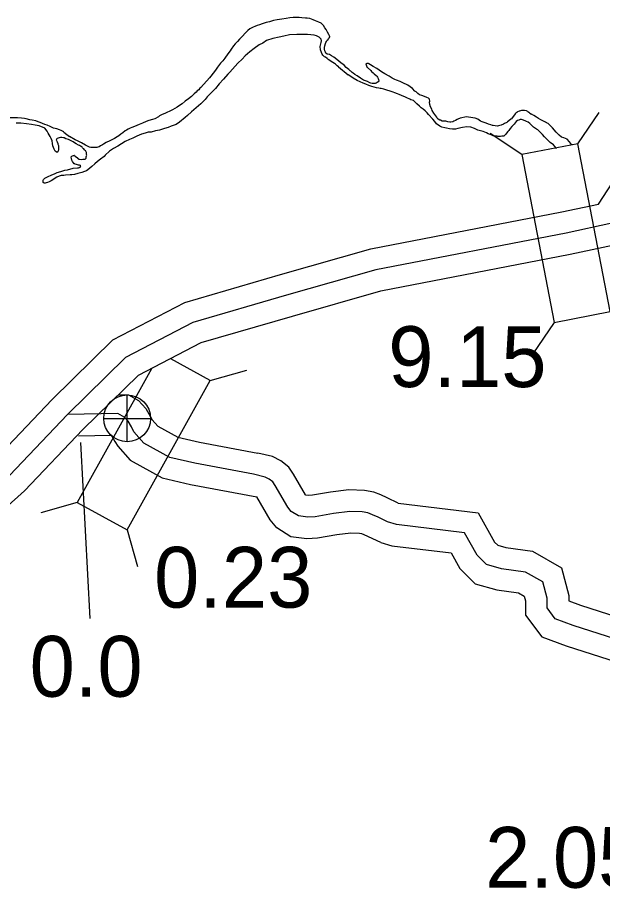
# Model space of a CAD drawing. Extents: x -83719 to 153526, y -11835 to 11446.
# Drawn here: x -4265.7 to -4130.2, y -1225.7 to -1023.9 of the extents above; entities that cross this region are included whole.
import ezdxf

# ---------------------------------------------------------------- set-up
doc = ezdxf.new("R2010")
doc.units = 0
for name, color, linetype in [('Level 10', 7, 'Continuous'), ('Level 20', 7, 'Continuous'), ('Level 25', 7, 'Continuous'), ('Level 26', 7, 'Continuous'), ('Level 58', 7, 'Continuous'), ('Level 59', 7, 'Continuous'), ('Level 9', 7, 'Continuous')]:
    doc.layers.add(name, color=color, linetype=linetype)

msp = doc.modelspace()

# ---------------------------------------------------------------- linework, layer by layer
at = {"layer": 'Level 10'}
msp.add_line((-4243.2, -1122.18), (-4242.49, -1123.21), dxfattribs=at)
for points in [[(-4271.03, -1126.42), (-4257.71, -1112.38), (-4243.65, -1098.56), (-4226.95, -1089.91), (-4204.78, -1083.46), (-4183.91, -1077.51), (-4139.71, -1068.96), (-4131.18, -1067.13), (-4120.41, -1050.53), (-4118.86, -1047.55), (-4114.95, -1043.07), (-4110.13, -1040.96), (-4104.85, -1040.74), (-4096.35, -1040.89), (-4088.26, -1041.21), (-4080.02, -1042.14), (-4050.59, -1033.6), (-4044.72, -1032.42), (-4008.49, -1036.91), (-3996.25, -1040.57)], [(-4268.64, -1137.7), (-4264.05, -1133.6), (-4250.57, -1119.39), (-4237.71, -1106.75), (-4223.21, -1099.24), (-4202.01, -1093.07), (-4181.59, -1087.25), (-4137.71, -1078.76), (-4125.04, -1076.04), (-4111.76, -1055.57), (-4110.54, -1053.23), (-4108.89, -1051.34), (-4107.84, -1050.88), (-4104.73, -1050.75), (-4096.64, -1050.89), (-4089.02, -1051.19), (-4079.15, -1052.3), (-4048.21, -1043.32), (-4044.34, -1042.55), (-4010.55, -1046.73), (-3999.11, -1050.15)], [(-4242.33, -1111.32), (-4240.01, -1111.3), (-4237.7, -1112.62), (-4235.96, -1114.48), (-4234.54, -1117.11)], [(-4234.54, -1117.11), (-4233.25, -1118.56), (-4228.61, -1121.14), (-4223.6, -1122.29), (-4210.05, -1124.85)], [(-4251.56, -1120.83), (-4243.98, -1120.68)], [(-4243.98, -1120.68), (-4243.75, -1121.1), (-4243.2, -1122.18)], [(-4242.49, -1123.21), (-4239.6, -1126.47), (-4232.23, -1130.57), (-4225.66, -1132.08), (-4210.31, -1134.98)], [(-4177.54, -1136.41), (-4180.1, -1135.18), (-4181.59, -1134.5), (-4183.23, -1133.89), (-4185.33, -1133.47), (-4189.02, -1133.34), (-4193.25, -1133.9), (-4197.39, -1134.59), (-4198.33, -1134.65), (-4198.93, -1134.57), (-4199.02, -1134.51), (-4199.02, -1134.51), (-4201.82, -1129.69), (-4202.89, -1128.09), (-4204.71, -1126.63), (-4206.66, -1125.65), (-4210.05, -1124.85)], [(-4181.6, -1145.51), (-4185.43, -1143.74), (-4185.97, -1143.54), (-4186.49, -1143.43), (-4188.54, -1143.36), (-4191.77, -1143.79), (-4196.26, -1144.54), (-4198.69, -1144.69), (-4202.39, -1144.2), (-4205.67, -1142.15), (-4207.24, -1140.27), (-4210.31, -1134.98)], [(-4177.54, -1136.41), (-4159.05, -1138.66), (-4155.25, -1145.45), (-4154.51, -1146.19), (-4152.63, -1146.73), (-4146.48, -1147.58), (-4139.75, -1151.38), (-4138.08, -1157.84), (-4138.08, -1159.04), (-4138.08, -1159.05), (-4135.37, -1160.08), (-4109.86, -1168.26), (-4103.97, -1180.37), (-4102.15, -1182.77), (-4098.56, -1184.79), (-4092.35, -1186.67), (-4087.42, -1189.5), (-4086.63, -1189.57), (-4073.87, -1188.11), (-4053.9, -1180.49), (-4031.8, -1175.51), (-4007.33, -1172.49), (-3998.66, -1171.4), (-3993.94, -1172.24)], [(-4181.6, -1145.51), (-4179.03, -1146.3), (-4165.3, -1147.97), (-4163.3, -1151.55), (-4159.74, -1155.1), (-4154.7, -1156.54), (-4149.74, -1157.22), (-4148.37, -1158), (-4148.08, -1159.09), (-4148.1, -1162.35), (-4144.34, -1167.37), (-4138.67, -1169.52), (-4116.98, -1176.48)]]:
    msp.add_lwpolyline(points, dxfattribs=at)
at = {"layer": 'Level 20'}
for p, q in [((-4135.99, -1053.17), (-4131.06, -1045.88)), ((-4148.95, -1055.67), (-4156.24, -1050.75)), ((-4141.43, -1094.55), (-4146.36, -1101.84)), ((-4221.1, -1108.03), (-4230.21, -1102.97)), ((-4234.67, -1105.27), (-4251.86, -1136.25)), ((-4221.1, -1108.03), (-4212.64, -1105.61)), ((-4240.32, -1142.65), (-4221.1, -1108.03)), ((-4251.86, -1136.25), (-4260.32, -1138.67)), ((-4251.86, -1136.25), (-4240.32, -1142.65)), ((-4240.32, -1142.65), (-4237.9, -1151.11))]:
    msp.add_line(p, q, dxfattribs=at)
msp.add_lwpolyline([(-4148.95, -1055.67), (-4141.43, -1094.55), (-4128.47, -1092.05), (-4135.99, -1053.17)], close=True, dxfattribs=at)
at = {"layer": 'Level 25'}
msp.add_line((-4251.13, -1122.41), (-4248.99, -1163.16), dxfattribs=at)
at = {"layer": 'Level 26'}
for p, q in [((-4240.32, -1122.21), (-4240.32, -1111.37)), ((-4245.73, -1116.79), (-4234.9, -1116.79))]:
    msp.add_line(p, q, dxfattribs=at)
msp.add_circle((-4240.32, -1116.79), 5.42, dxfattribs=at)
at = {"layer": 'Level 59'}
for points in [[(-3997.68, -1045.36), (-4009.52, -1041.82), (-4044.53, -1037.49), (-4049.4, -1038.46), (-4079.58, -1047.22), (-4088.64, -1046.2), (-4096.49, -1045.89), (-4104.79, -1045.74), (-4108.98, -1045.92), (-4111.92, -1047.2), (-4114.7, -1050.39), (-4116.08, -1053.05), (-4128.11, -1071.59), (-4138.71, -1073.86), (-4182.75, -1082.38), (-4203.4, -1088.26), (-4225.08, -1094.57), (-4240.68, -1102.65), (-4254.14, -1115.88), (-4267.54, -1130.01)], [(-4242.48, -1115.65), (-4254.14, -1115.88)], [(-4238.75, -1119.9), (-4239.32, -1118.77), (-4240.05, -1117.43), (-4240.84, -1116.58), (-4242.48, -1115.65)], [(-4211.09, -1129.75), (-4224.63, -1127.19), (-4230.42, -1125.85), (-4236.43, -1122.52), (-4238.75, -1119.9)], [(-4180.03, -1140.76), (-4182.23, -1139.71), (-4183.51, -1139.12), (-4184.6, -1138.71), (-4185.91, -1138.45), (-4188.78, -1138.35), (-4192.51, -1138.84), (-4196.82, -1139.57), (-4198.51, -1139.67), (-4200.66, -1139.38), (-4202.34, -1138.33), (-4203.13, -1137.39), (-4206.06, -1132.34), (-4206.62, -1131.5), (-4207.42, -1130.86), (-4208.37, -1130.39), (-4211.09, -1129.75)], [(-4113.42, -1172.37), (-4137.02, -1164.8), (-4141.21, -1163.21), (-4143.09, -1160.7), (-4143.08, -1158.46), (-4144.06, -1154.69), (-4148.11, -1152.4), (-4153.67, -1151.63), (-4157.12, -1150.65), (-4159.28, -1148.5), (-4162.18, -1143.32), (-4177.99, -1141.39), (-4180.03, -1140.76)]]:
    msp.add_lwpolyline(points, dxfattribs=at)
at = {"layer": 'Level 9'}
for points in [[(-4184.82, -1034.55), (-4184.95, -1034.62), (-4185.02, -1034.65), (-4184.98, -1034.88), (-4184.85, -1035.32), (-4184.79, -1035.38), (-4184.69, -1035.52), (-4183.89, -1036.22), (-4183.76, -1036.39), (-4183.36, -1036.76), (-4183.1, -1036.99), (-4182.7, -1037.33), (-4182.53, -1037.5), (-4182.34, -1037.7), (-4182.2, -1038), (-4182.11, -1038.23), (-4182.07, -1038.57), (-4182.07, -1038.6), (-4182.21, -1038.83), (-4182.41, -1038.93), (-4182.44, -1039), (-4182.68, -1039.1), (-4182.91, -1039.16), (-4183.28, -1039.16), (-4183.58, -1039.16), (-4183.88, -1039.12), (-4184.11, -1039.06), (-4184.67, -1038.75), (-4185.34, -1038.52), (-4185.57, -1038.41), (-4186.03, -1038.14), (-4186.3, -1037.98), (-4187.06, -1037.44), (-4187.59, -1037.07), (-4187.99, -1036.83), (-4188.19, -1036.67), (-4188.56, -1036.33), (-4188.65, -1036.23), (-4189.02, -1035.96), (-4189.62, -1035.46), (-4190.08, -1034.95), (-4190.88, -1034.38), (-4191.34, -1034.05), (-4191.77, -1033.64), (-4192.47, -1033.11), (-4193.03, -1032.8), (-4193.5, -1032.5), (-4194.03, -1032.36), (-4194.29, -1032.2), (-4194.43, -1031.96), (-4194.52, -1031.66), (-4194.59, -1031.23), (-4194.59, -1030.86), (-4194.52, -1030.46), (-4194.41, -1029.96), (-4194.28, -1029.66), (-4194.18, -1029.5), (-4193.98, -1029.16), (-4193.81, -1029), (-4193.67, -1028.8), (-4193.64, -1028.77), (-4193.54, -1028.6), (-4193.37, -1028.4), (-4193.41, -1028.27), (-4193.47, -1028.13), (-4193.64, -1027.83), (-4193.9, -1027.33), (-4194.26, -1026.69), (-4194.56, -1026.26), (-4194.86, -1025.72), (-4195.06, -1025.56), (-4195.42, -1025.19), (-4195.95, -1024.95), (-4196.72, -1024.65), (-4197.28, -1024.48), (-4198.04, -1024.14), (-4198.61, -1024.07), (-4199.04, -1024.07), (-4199.91, -1023.99), (-4200.47, -1023.92), (-4200.97, -1023.89), (-4201.41, -1023.89), (-4201.87, -1023.88), (-4202.67, -1024.01), (-4203.47, -1024.11), (-4204.47, -1024.27), (-4205.57, -1024.43), (-4206.41, -1024.62), (-4207.34, -1024.89), (-4208.11, -1025.08), (-4209.07, -1025.38), (-4209.64, -1025.57), (-4210.24, -1025.74), (-4210.74, -1025.97), (-4211.11, -1026.13), (-4211.88, -1026.53), (-4212.38, -1026.89), (-4212.98, -1027.52), (-4213.59, -1028.22), (-4214.29, -1028.95), (-4214.76, -1029.44)], [(-4191.35, -1035.33), (-4191.68, -1035.08), (-4192.11, -1034.74), (-4192.34, -1034.57), (-4193.1, -1034.07), (-4193.64, -1033.7), (-4193.67, -1033.67), (-4193.83, -1033.57), (-4194.03, -1033.43), (-4194.43, -1033.13), (-4194.63, -1032.99), (-4195.03, -1032.63), (-4195.19, -1032.36), (-4195.32, -1031.99), (-4195.55, -1031.42), (-4195.62, -1030.62), (-4195.38, -1029.69), (-4195.34, -1029.29), (-4195.37, -1028.89), (-4195.84, -1028.49), (-4196.17, -1028.32), (-4196.44, -1028.18), (-4197, -1028.01), (-4198.53, -1027.84), (-4199.86, -1027.83), (-4201.06, -1027.86), (-4202.73, -1027.95), (-4204.03, -1028.24), (-4205.13, -1028.47), (-4206.6, -1028.76), (-4208.03, -1029.25), (-4208.9, -1029.85), (-4209.73, -1030.24), (-4210.9, -1031.1), (-4211.94, -1031.83), (-4213.01, -1032.76), (-4213.72, -1033.55), (-4214.69, -1034.48), (-4216.53, -1036.57), (-4217, -1037.03), (-4218, -1038.2), (-4218.98, -1039.29), (-4219.88, -1040.39), (-4220.59, -1041.08), (-4221.76, -1042.28), (-4222.26, -1042.87), (-4223.26, -1043.87), (-4224.34, -1044.86), (-4225.41, -1045.79), (-4226.31, -1046.62), (-4226.85, -1047.05), (-4228.22, -1048.14), (-4228.95, -1048.67), (-4230.09, -1049.06), (-4230.86, -1049.36), (-4231.69, -1049.62), (-4232.79, -1049.98), (-4233.72, -1050.18), (-4234.76, -1050.44), (-4235.42, -1050.5), (-4236.16, -1050.73), (-4236.96, -1050.96), (-4238.06, -1051.39), (-4239.03, -1051.85), (-4239.8, -1052.18), (-4240.76, -1052.6), (-4241.63, -1053.17), (-4242.47, -1053.73), (-4243.47, -1054.26), (-4244.37, -1054.88), (-4245.38, -1055.78), (-4245.65, -1056.11), (-4246.48, -1056.74), (-4247.15, -1057.24), (-4247.82, -1057.83), (-4248.46, -1058.43), (-4248.96, -1058.83), (-4249.43, -1059.19), (-4249.73, -1059.42), (-4250.19, -1059.59), (-4250.8, -1059.82)], [(-4214.76, -1029.44), (-4215.33, -1030.01), (-4215.7, -1030.44), (-4216.23, -1031.24), (-4216.47, -1031.6), (-4216.97, -1032.33), (-4217.71, -1033.3), (-4218.18, -1033.93), (-4218.68, -1034.49), (-4219.39, -1035.42), (-4219.86, -1036.08), (-4220.43, -1036.81), (-4220.96, -1037.48), (-4221.27, -1037.88)], [(-4191.35, -1035.33), (-4189.17, -1037.15)], [(-4147.71, -1045.57), (-4147.84, -1045.53), (-4147.91, -1045.53), (-4148.34, -1045.46), (-4148.64, -1045.43), (-4149.01, -1045.43), (-4149.21, -1045.49), (-4149.44, -1045.59), (-4149.58, -1045.62), (-4149.91, -1045.75), (-4150.11, -1045.89), (-4150.31, -1046.05), (-4150.51, -1046.25), (-4151.32, -1047.38), (-4151.45, -1047.45), (-4151.92, -1047.81), (-4152.22, -1048.07), (-4152.42, -1048.24), (-4152.96, -1048.5), (-4153.19, -1048.64), (-4153.72, -1048.83), (-4154.02, -1048.96), (-4154.32, -1049.03), (-4154.56, -1049.06), (-4155.09, -1049.03), (-4155.56, -1048.92), (-4155.76, -1048.89), (-4156.15, -1048.75), (-4156.62, -1048.62), (-4157.22, -1048.41), (-4157.62, -1048.24), (-4158.15, -1048.04), (-4158.48, -1047.91), (-4159.14, -1047.47), (-4159.74, -1047.26), (-4160.28, -1047.13), (-4160.74, -1047.06), (-4161.81, -1046.92), (-4162.11, -1046.98), (-4162.81, -1047.15), (-4163.21, -1047.24), (-4163.77, -1047.48), (-4163.94, -1047.54), (-4164.31, -1047.74), (-4164.68, -1047.94), (-4164.94, -1048.04), (-4165.34, -1048.13), (-4165.64, -1048.13), (-4166.08, -1048.06), (-4166.51, -1047.96), (-4167.11, -1047.96), (-4167.41, -1047.89), (-4167.8, -1047.72), (-4167.94, -1047.68), (-4168.3, -1047.48), (-4168.4, -1047.42), (-4168.6, -1046.98), (-4169.1, -1046.38), (-4169.29, -1046.04), (-4169.66, -1045.44), (-4169.79, -1045.14), (-4170.05, -1044.57), (-4170.22, -1044.07), (-4170.28, -1043.54), (-4170.21, -1043.27), (-4170.31, -1042.8), (-4170.51, -1042.6), (-4170.91, -1042.43), (-4171.5, -1042.2), (-4172.07, -1041.99), (-4172.6, -1041.79), (-4173.03, -1041.49), (-4173.43, -1041.15), (-4173.73, -1040.95), (-4174.22, -1040.38), (-4174.79, -1039.94), (-4175.32, -1039.61), (-4176.51, -1039.03), (-4177.11, -1038.76), (-4177.94, -1038.39), (-4178.31, -1038.26), (-4178.97, -1037.95), (-4179.64, -1037.51), (-4180.67, -1036.94), (-4181.06, -1036.74), (-4181.43, -1036.47), (-4181.96, -1036.1), (-4182.49, -1035.73), (-4183.32, -1035.26), (-4183.98, -1034.86), (-4184.35, -1034.65), (-4184.45, -1034.59), (-4184.55, -1034.59), (-4184.68, -1034.55), (-4184.78, -1034.55), (-4184.82, -1034.55)], [(-4178.72, -1041.22), (-4180.89, -1040.51), (-4181.48, -1040.34), (-4181.62, -1040.34), (-4181.75, -1040.34), (-4182.05, -1040.27), (-4182.62, -1040.2), (-4183.68, -1039.89), (-4184.38, -1039.62), (-4185.04, -1039.35), (-4185.71, -1039.08), (-4186.34, -1038.84), (-4187.04, -1038.51), (-4187.96, -1037.93), (-4188.53, -1037.56), (-4189.17, -1037.15)], [(-4221.27, -1037.88), (-4223.28, -1040.1), (-4223.48, -1040.3), (-4223.71, -1040.66), (-4224.08, -1040.93), (-4224.35, -1041.19), (-4224.78, -1041.62), (-4225.39, -1042.19), (-4226.09, -1042.72), (-4226.92, -1043.28), (-4227.56, -1043.91), (-4228.2, -1044.27), (-4228.7, -1044.64), (-4229.3, -1044.97), (-4229.8, -1045.3), (-4230.47, -1045.63), (-4231.14, -1045.92), (-4231.57, -1046.15), (-4232.24, -1046.38), (-4232.81, -1046.68), (-4233.07, -1046.91), (-4233.91, -1047.37), (-4234.44, -1047.54), (-4235.31, -1047.77), (-4235.94, -1048), (-4236.74, -1048.36), (-4237.55, -1048.72), (-4238.08, -1048.92), (-4239.01, -1049.31), (-4239.21, -1049.41), (-4239.65, -1049.54), (-4240.12, -1049.77), (-4240.48, -1049.97), (-4240.75, -1050.17), (-4241.32, -1050.6), (-4241.75, -1050.93), (-4242.22, -1051.3), (-4242.66, -1051.56), (-4243.22, -1051.92), (-4243.43, -1052.02), (-4243.86, -1052.25), (-4244.33, -1052.48), (-4245.16, -1052.88), (-4245.76, -1053.28), (-4246.03, -1053.44), (-4246.5, -1053.67), (-4246.83, -1053.87), (-4247.07, -1053.93), (-4247.33, -1054), (-4247.63, -1054.03), (-4248.07, -1054.03), (-4248.33, -1054.03), (-4248.7, -1053.99), (-4249.03, -1053.92), (-4249.46, -1053.75), (-4249.99, -1053.48), (-4250.36, -1053.28), (-4250.49, -1053.15), (-4250.89, -1052.95), (-4251.85, -1052.51), (-4252.35, -1052.24), (-4253.68, -1051.46)], [(-4154.47, -1051.5), (-4154.67, -1051.43), (-4155.1, -1051.36), (-4155.54, -1051.32), (-4156.03, -1051.12), (-4156.7, -1050.82), (-4157.13, -1050.65), (-4157.9, -1050.28), (-4158.53, -1050.14), (-4159.09, -1049.97), (-4159.92, -1049.63), (-4160.75, -1049.29), (-4161.65, -1049.25), (-4162.65, -1049.38), (-4163.79, -1049.64), (-4164.29, -1049.74), (-4165.02, -1049.74), (-4165.72, -1049.66), (-4166.38, -1049.56), (-4166.78, -1049.46), (-4167.45, -1049.29), (-4167.95, -1049.05), (-4168.68, -1048.55), (-4169.07, -1048.01), (-4169.54, -1047.48), (-4170.56, -1046.4), (-4170.89, -1046), (-4171.32, -1045.53), (-4171.75, -1045.16), (-4172.22, -1044.83), (-4172.65, -1044.46), (-4173.21, -1043.92), (-4173.58, -1043.58), (-4174.04, -1043.15), (-4174.67, -1042.94), (-4174.87, -1042.81), (-4175.54, -1042.51), (-4175.9, -1042.37), (-4176.76, -1042), (-4177.33, -1041.76), (-4177.76, -1041.56), (-4178.36, -1041.32), (-4178.72, -1041.22)], [(-4147.71, -1045.57), (-4147.55, -1045.68), (-4147.35, -1045.83), (-4147.11, -1046.03), (-4146.68, -1046.27)], [(-4254.94, -1050.44), (-4254.97, -1050.42), (-4255.57, -1050.12), (-4255.97, -1049.92), (-4256.57, -1049.71), (-4257.36, -1049.51), (-4258.16, -1049.14), (-4258.86, -1048.87), (-4259.36, -1048.66), (-4259.89, -1048.43), (-4260.49, -1048.22), (-4260.92, -1048.09), (-4261.49, -1047.88), (-4262.28, -1047.71), (-4262.82, -1047.58), (-4263.68, -1047.4), (-4264.08, -1047.34), (-4264.81, -1047.23), (-4265.71, -1047.13), (-4266.21, -1047.12), (-4266.84, -1047.12), (-4268.37, -1047.18), (-4268.84, -1047.18), (-4269.27, -1047.17)], [(-4140.92, -1054.22), (-4141, -1054.14), (-4141.23, -1053.84), (-4141.63, -1053.44), (-4142.39, -1052.9), (-4143.15, -1052.09), (-4143.68, -1051.59), (-4144.15, -1050.99), (-4144.68, -1050.49), (-4144.94, -1050.22), (-4145.24, -1049.95), (-4145.54, -1049.75), (-4146.23, -1049.31), (-4147.1, -1048.47), (-4147.49, -1048.17), (-4147.82, -1047.97), (-4148.19, -1047.83), (-4148.76, -1047.63), (-4148.99, -1047.56), (-4149.29, -1047.56), (-4149.65, -1047.69), (-4149.92, -1047.79), (-4150.22, -1048.02), (-4150.49, -1048.28), (-4150.73, -1048.65), (-4151.23, -1049.18), (-4151.63, -1049.65), (-4151.97, -1050.11), (-4152.17, -1050.34), (-4152.47, -1050.74), (-4152.74, -1051.04), (-4153.07, -1051.4), (-4153.54, -1051.43), (-4153.84, -1051.47), (-4154.11, -1051.5), (-4154.47, -1051.5)], [(-4138.42, -1052.12), (-4139.22, -1051.82), (-4139.79, -1051.61), (-4140.32, -1051.14), (-4140.95, -1050.44), (-4141.87, -1049.47), (-4142.53, -1048.8), (-4142.87, -1048.49), (-4143.23, -1048.29), (-4143.46, -1048.16), (-4143.93, -1047.92), (-4144.53, -1047.65), (-4145.09, -1047.31), (-4145.52, -1046.98), (-4146.19, -1046.58), (-4146.68, -1046.27)], [(-4256.4, -1053.09), (-4256.35, -1053.22), (-4256.25, -1053.55), (-4256.19, -1053.75), (-4256.19, -1053.78), (-4256.19, -1054.02), (-4256.23, -1054.45), (-4256.23, -1054.62), (-4256.26, -1054.78), (-4256.33, -1054.95), (-4256.4, -1055.05), (-4256.46, -1055.12), (-4256.56, -1055.11), (-4256.66, -1055.11), (-4256.76, -1055.05), (-4256.96, -1054.91), (-4257.03, -1054.75), (-4257.23, -1054.44), (-4257.52, -1053.64), (-4257.58, -1053.07), (-4257.71, -1052.44), (-4257.94, -1051.97), (-4258.17, -1051.47), (-4258.6, -1050.7), (-4258.83, -1050.2), (-4259.36, -1049.53), (-4260.66, -1049.02), (-4261.59, -1048.85), (-4262.46, -1048.71), (-4263.65, -1048.54), (-4264.95, -1048.4), (-4266.05, -1048.39)], [(-4254.94, -1050.44), (-4254.28, -1051.04), (-4253.68, -1051.46)], [(-4249.9, -1054.82), (-4250, -1054.69), (-4250.17, -1054.55), (-4250.33, -1054.35), (-4250.5, -1054.22), (-4250.66, -1054.08), (-4250.73, -1053.98), (-4250.96, -1053.81), (-4251.13, -1053.71), (-4251.36, -1053.58), (-4251.56, -1053.51), (-4252.12, -1053.17), (-4252.49, -1052.97), (-4252.79, -1052.74), (-4253.15, -1052.53), (-4253.45, -1052.4), (-4253.92, -1052.2), (-4254.51, -1051.99), (-4254.88, -1051.82), (-4255.05, -1051.76), (-4255.45, -1051.72), (-4255.78, -1051.68), (-4256.08, -1051.78), (-4256.28, -1051.85), (-4256.51, -1051.95), (-4256.68, -1052.08), (-4256.71, -1052.15), (-4256.75, -1052.31), (-4256.67, -1052.42)], [(-4256.67, -1052.42), (-4256.53, -1052.74), (-4256.4, -1053.09)], [(-4137.32, -1053.43), (-4137.4, -1053.29), (-4137.93, -1052.72), (-4138.42, -1052.12)], [(-4250.8, -1059.82), (-4251.76, -1060.04), (-4252.53, -1060.27), (-4253.1, -1060.34), (-4253.53, -1060.37), (-4254.56, -1060.43), (-4254.96, -1060.49), (-4255.56, -1060.52), (-4256.03, -1060.65), (-4256.56, -1060.88), (-4257.9, -1061.71), (-4258.37, -1062.01), (-4258.77, -1062.14), (-4259.1, -1062.2), (-4259.27, -1062.27), (-4259.4, -1062.3), (-4259.53, -1062.27), (-4259.73, -1062.17), (-4259.77, -1062.03), (-4259.77, -1061.93), (-4259.8, -1061.73), (-4259.8, -1061.66), (-4259.76, -1061.56), (-4259.7, -1061.47), (-4259.6, -1061.33), (-4259.49, -1061.23), (-4259.36, -1061.13), (-4259.23, -1061.07), (-4258.59, -1060.74), (-4257.93, -1060.41), (-4257.02, -1060.05), (-4256.52, -1059.82), (-4255.69, -1059.55), (-4254.75, -1059.26), (-4254.16, -1059.16), (-4252.82, -1058.84), (-4251.82, -1058.74), (-4251.59, -1058.74), (-4251.45, -1058.68), (-4251.35, -1058.65), (-4251.19, -1058.58), (-4251.09, -1058.48), (-4251.09, -1058.45), (-4251.09, -1058.41), (-4251.09, -1058.35), (-4251.05, -1058.25), (-4251.09, -1058.25), (-4251.09, -1058.21), (-4251.15, -1058.21), (-4251.35, -1058.11), (-4251.52, -1058.08), (-4251.62, -1058.08), (-4251.85, -1058.01), (-4252.05, -1057.94), (-4252.32, -1057.87), (-4252.45, -1057.81), (-4252.55, -1057.77), (-4252.71, -1057.57), (-4252.98, -1057.3), (-4253.14, -1056.93), (-4253.24, -1056.57), (-4253.31, -1056.3), (-4253.31, -1056.2), (-4253.21, -1056.1), (-4253.14, -1056.03), (-4253.1, -1056), (-4253, -1055.97), (-4252.74, -1055.84), (-4252.74, -1055.87), (-4252.64, -1055.87), (-4252.6, -1055.9), (-4252.54, -1055.9), (-4252.57, -1055.9), (-4252.51, -1055.94), (-4252.41, -1055.97), (-4252.34, -1056.01), (-4252.24, -1056.07), (-4251.87, -1056.37), (-4251.81, -1056.41), (-4251.78, -1056.48), (-4251.44, -1056.71), (-4250.91, -1056.78), (-4250.61, -1056.75), (-4250.25, -1056.75), (-4250.21, -1056.75), (-4250.05, -1056.72), (-4250.04, -1056.69), (-4249.84, -1056.49), (-4249.81, -1056.49), (-4249.84, -1056.35), (-4249.81, -1056.22), (-4249.78, -1056.15), (-4249.71, -1055.92), (-4249.67, -1055.79), (-4249.71, -1055.62), (-4249.71, -1055.49), (-4249.7, -1055.32), (-4249.7, -1055.22), (-4249.74, -1055.15), (-4249.87, -1054.89), (-4249.9, -1054.82)]]:
    msp.add_lwpolyline(points, dxfattribs=at)

# ---------------------------------------------------------------- texts
at = {"layer": 'Level 25'}
msp.add_text('0.0', height=14.08, dxfattribs=at).set_placement((-4262.9, -1181.28))
at = {"layer": 'Level 58'}
for s, p in [('9.15', (-4179.87, -1109.53)), ('0.23', (-4234.08, -1160.64)), ('2.05', (-4157.44, -1225.54))]:
    msp.add_text(s, height=14.08, dxfattribs=at).set_placement(p)

doc.saveas('drawing.dxf')
